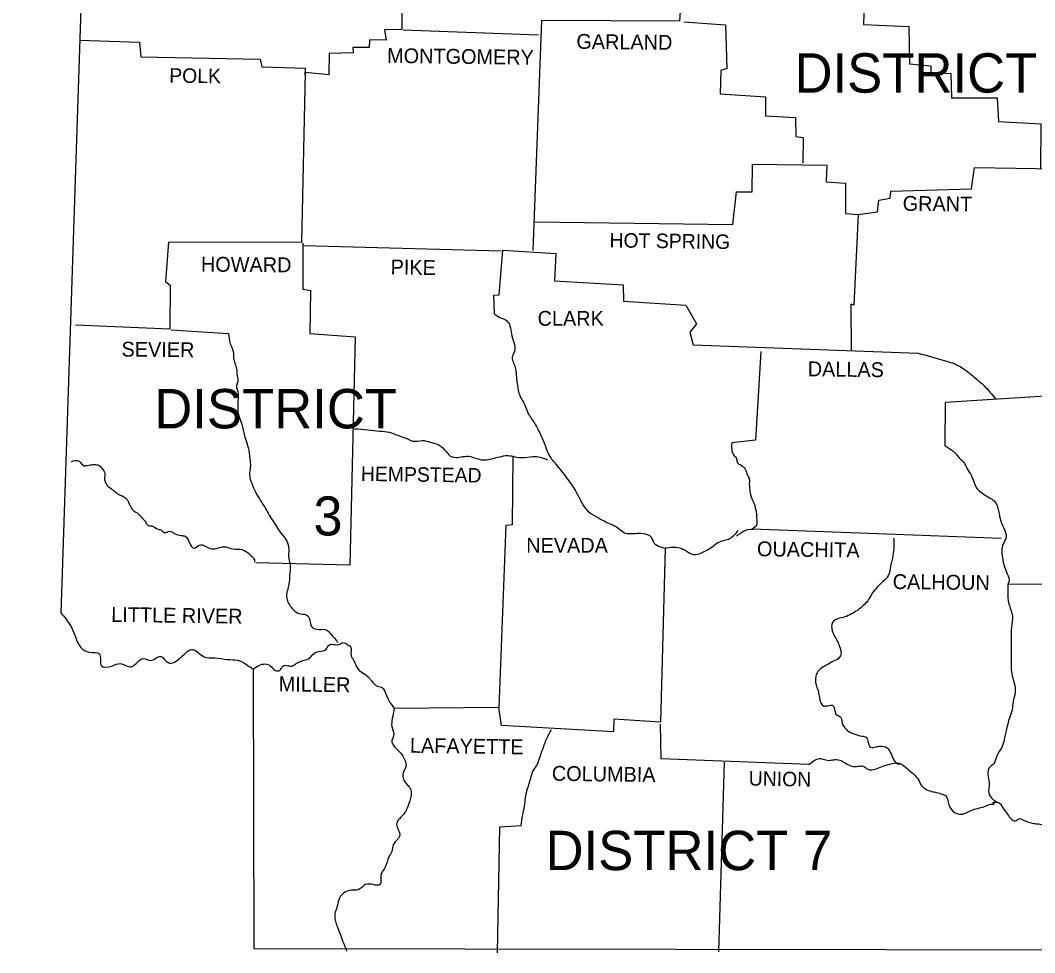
# Model space of a CAD drawing. Extents: x 1671357 to 13005564, y 567358 to 14261451.
# Drawn here: x 12758312.079 to 12758315.016, y 14259950.411 to 14259953.11 of the extents above; entities that cross this region are included whole.
import ezdxf

# ---------------------------------------------------------------- set-up
doc = ezdxf.new("R2010")
doc.units = 0
doc.layers.add('Default', color=7, linetype='Continuous')

msp = doc.modelspace()

# ---------------------------------------------------------------- linework, layer by layer
at = {"layer": 'Default'}
for points in [[(12758312.079, 14259955.7696), (12758312.286, 14259954.1076), (12758312.196, 14259951.3946)], [(12758313.186, 14259953.6686), (12758313.184, 14259953.0836), (12758313.134, 14259953.0826), (12758313.138, 14259953.0526), (12758313.09, 14259953.0536), (12758313.089, 14259953.0316), (12758313.042, 14259953.0316), (12758313.043, 14259953.0156), (12758312.973, 14259953.0136), (12758312.972, 14259952.9526), (12758312.904, 14259952.9586), (12758312.893, 14259952.4666), (12758312.508, 14259952.4676), (12758312.499, 14259952.3536), (12758312.513, 14259952.3436), (12758312.512, 14259952.2156), (12758312.239, 14259952.2276)], [(12758314.324, 14259953.2266), (12758313.997, 14259953.2366), (12758313.988, 14259953.1076), (12758313.588, 14259953.1096), (12758313.563, 14259952.4436)], [(12758314.413, 14259953.2296), (12758314.525, 14259953.2226), (12758314.521, 14259953.0976), (12758314.652, 14259953.0926), (12758314.654, 14259952.9836), (12758314.716, 14259952.9786), (12758314.716, 14259952.9596), (12758314.774, 14259952.9556), (12758314.776, 14259952.8856), (12758314.908, 14259952.8856), (12758314.912, 14259952.8166), (12758315.034, 14259952.8106), (12758315.033, 14259952.6806)], [(12758313.58, 14259953.0666), (12758313.188, 14259953.0816)], [(12758314, 14259953.1056), (12758314.121, 14259953.0966), (12758314.125, 14259952.9706), (12758314.108, 14259952.9646), (12758314.106, 14259952.8976), (12758314.237, 14259952.8886), (12758314.237, 14259952.8336), (12758314.324, 14259952.8286), (12758314.325, 14259952.7736), (12758314.346, 14259952.7706), (12758314.345, 14259952.6966)], [(12758312.251, 14259953.0526), (12758312.424, 14259953.0466), (12758312.428, 14259953.0046), (12758312.774, 14259952.9976), (12758312.778, 14259952.9756), (12758312.904, 14259952.9716), (12758312.903, 14259952.9526)], [(12758316.226, 14259952.7956), (12758315.848, 14259952.8056), (12758315.846, 14259952.6826), (12758315.081, 14259952.6796), (12758315.075, 14259952.2736), (12758315.052, 14259952.2726), (12758315.049, 14259952.0216), (12758314.757, 14259952.0036), (12758314.756, 14259951.8786)], [(12758313.57, 14259952.5266), (12758314.142, 14259952.5186), (12758314.153, 14259952.6136), (12758314.198, 14259952.6136), (12758314.199, 14259952.6936), (12758314.415, 14259952.6906), (12758314.413, 14259952.6426), (12758314.469, 14259952.6386), (12758314.469, 14259952.5506), (12758314.505, 14259952.5476), (12758314.493, 14259952.2856), (12758314.484, 14259952.2886), (12758314.485, 14259952.1526)], [(12758314.505, 14259952.5476), (12758314.561, 14259952.5556), (12758314.565, 14259952.5896), (12758314.598, 14259952.5956), (12758314.6, 14259952.6156), (12758314.833, 14259952.6226), (12758314.842, 14259952.6836), (12758315.081, 14259952.6796)], [(12758312.897, 14259952.4646), (12758312.897, 14259952.3316), (12758312.919, 14259952.3276), (12758312.917, 14259952.2036), (12758313.049, 14259952.1936), (12758313.033, 14259951.5326), (12758312.761, 14259951.5396)], [(12758312.899, 14259952.4576), (12758313.471, 14259952.4426)], [(12758313.452, 14259952.2596), (12758313.45, 14259952.3146), (12758313.466, 14259952.3156), (12758313.476, 14259952.4446), (12758313.63, 14259952.4346), (12758313.626, 14259952.3556), (12758313.825, 14259952.3446), (12758313.826, 14259952.2966), (12758314.006, 14259952.2856), (12758314.037, 14259952.2316), (12758314.018, 14259952.2076), (12758314.027, 14259952.1706), (12758314.679, 14259952.1466)], [(12758312.516, 14259952.2136), (12758312.682, 14259952.2036)], [(12758314.223, 14259952.1516), (12758314.208, 14259951.8946), (12758314.139, 14259951.8866)], [(12758313.505, 14259951.8486), (12758313.503, 14259951.6496), (12758313.485, 14259951.6476), (12758313.465, 14259951.1206)], [(12758314.198, 14259951.6376), (12758314.612, 14259951.6226), (12758314.919, 14259951.6106)], [(12758313.946, 14259951.5816), (12758313.933, 14259951.0776), (12758313.798, 14259951.0866), (12758313.797, 14259951.0496), (12758313.472, 14259951.0686), (12758313.465, 14259951.1206), (12758313.162, 14259951.1176)], [(12758314.939, 14259951.4776), (12758315.391, 14259951.4786), (12758315.381, 14259951.2006), (12758315.359, 14259951.1866)], [(12758312.753, 14259951.2316), (12758312.755, 14259950.4226), (12758316.42, 14259950.4166)], [(12758314.362, 14259950.9556), (12758313.935, 14259950.9716), (12758313.933, 14259951.0726)], [(12758314.117, 14259950.9626), (12758314.101, 14259950.4136)], [(12758313.529, 14259950.7776), (12758313.467, 14259950.7736), (12758313.46, 14259950.4106)]]:
    msp.add_lwpolyline(points, dxfattribs=at)
for points in [[(12758313.452, 14259952.2596), (12758313.468, 14259952.2496), (12758313.487, 14259952.2406), (12758313.497, 14259952.2256), (12758313.501, 14259952.2026), (12758313.508, 14259952.1776), (12758313.51, 14259952.1516), (12758313.504, 14259952.1376), (12758313.512, 14259952.1056), (12758313.515, 14259952.0836), (12758313.518, 14259952.0576), (12758313.526, 14259952.0226), (12758313.539, 14259951.9986), (12758313.551, 14259951.9696), (12758313.571, 14259951.9386), (12758313.588, 14259951.9046), (12758313.596, 14259951.8866), (12758313.611, 14259951.8496), (12758313.63, 14259951.8246), (12758313.66, 14259951.7866), (12758313.687, 14259951.7476), (12758313.702, 14259951.7186), (12758313.725, 14259951.6866), (12758313.751, 14259951.6706), (12758313.784, 14259951.6536), (12758313.805, 14259951.6436), (12758313.829, 14259951.6266), (12758313.86, 14259951.6246), (12758313.883, 14259951.6246), (12758313.904, 14259951.6156), (12758313.914, 14259951.5976), (12758313.932, 14259951.5856), (12758313.946, 14259951.5816)], [(12758312.682, 14259952.2036), (12758312.687, 14259952.1736), (12758312.696, 14259952.1476), (12758312.697, 14259952.1276), (12758312.706, 14259952.0976), (12758312.706, 14259952.0866), (12758312.709, 14259952.0646), (12758312.705, 14259952.0526), (12758312.71, 14259952.0286), (12758312.709, 14259952.0106), (12758312.709, 14259951.9956), (12758312.71, 14259951.9706), (12758312.718, 14259951.9486), (12758312.726, 14259951.9156), (12758312.731, 14259951.8986), (12758312.739, 14259951.8726), (12758312.744, 14259951.8406), (12758312.745, 14259951.8166), (12758312.743, 14259951.7946), (12758312.749, 14259951.7696), (12758312.76, 14259951.7446), (12758312.774, 14259951.7206), (12758312.791, 14259951.6936), (12758312.803, 14259951.6726), (12758312.818, 14259951.6496), (12758312.83, 14259951.6306), (12758312.848, 14259951.6066), (12758312.856, 14259951.5866), (12758312.856, 14259951.5586), (12758312.86, 14259951.5326), (12758312.859, 14259951.5036), (12758312.857, 14259951.4776), (12758312.85, 14259951.4416), (12758312.855, 14259951.4246), (12758312.874, 14259951.3996), (12758312.886, 14259951.3926), (12758312.907, 14259951.3886), (12758312.917, 14259951.3746), (12758312.923, 14259951.3536), (12758312.944, 14259951.3466), (12758312.967, 14259951.3446), (12758312.978, 14259951.3326), (12758312.993, 14259951.3166), (12758312.998, 14259951.3086)], [(12758314.679, 14259952.1466), (12758314.757, 14259952.1246), (12758314.797, 14259952.1096), (12758314.837, 14259952.0806), (12758314.87, 14259952.0516), (12758314.903, 14259952.0146)], [(12758313.047, 14259951.9276), (12758313.085, 14259951.9246), (12758313.12, 14259951.9206), (12758313.147, 14259951.9176), (12758313.175, 14259951.9076), (12758313.2, 14259951.8986), (12758313.216, 14259951.8916), (12758313.243, 14259951.8936), (12758313.266, 14259951.8886), (12758313.292, 14259951.8796), (12758313.311, 14259951.8626), (12758313.323, 14259951.8496), (12758313.346, 14259951.8446), (12758313.365, 14259951.8476), (12758313.388, 14259951.8456), (12758313.414, 14259951.8376), (12758313.435, 14259951.8386), (12758313.452, 14259951.8426), (12758313.472, 14259951.8476), (12758313.497, 14259951.8496), (12758313.516, 14259951.8456), (12758313.541, 14259951.8446), (12758313.57, 14259951.8476), (12758313.606, 14259951.8376)], [(12758314.139, 14259951.8866), (12758314.139, 14259951.8676), (12758314.146, 14259951.8496), (12758314.153, 14259951.8416), (12758314.156, 14259951.8286), (12758314.165, 14259951.8226), (12758314.178, 14259951.8106), (12758314.185, 14259951.7936), (12758314.19, 14259951.7826), (12758314.19, 14259951.7686), (12758314.191, 14259951.7546), (12758314.193, 14259951.7376), (12758314.205, 14259951.7076), (12758314.208, 14259951.6956), (12758314.21, 14259951.6856), (12758314.211, 14259951.6686), (12758314.211, 14259951.6486), (12758314.198, 14259951.6376)], [(12758314.756, 14259951.8786), (12758314.779, 14259951.8636), (12758314.798, 14259951.8436), (12758314.812, 14259951.8286), (12758314.821, 14259951.8116), (12758314.833, 14259951.7916), (12758314.85, 14259951.7536), (12758314.865, 14259951.7406), (12758314.886, 14259951.7276), (12758314.899, 14259951.7186), (12758314.912, 14259951.6896), (12758314.918, 14259951.6606), (12758314.929, 14259951.6346), (12758314.934, 14259951.6146), (12758314.925, 14259951.5946), (12758314.923, 14259951.5546), (12758314.929, 14259951.5276), (12758314.937, 14259951.5076), (12758314.942, 14259951.4846), (12758314.939, 14259951.4776)], [(12758312.227, 14259951.8326), (12758312.249, 14259951.8336), (12758312.264, 14259951.8206), (12758312.273, 14259951.8216), (12758312.289, 14259951.8236), (12758312.304, 14259951.8226), (12758312.315, 14259951.8136), (12758312.324, 14259951.7976), (12758312.323, 14259951.7826), (12758312.324, 14259951.7766), (12758312.331, 14259951.7636), (12758312.343, 14259951.7536), (12758312.356, 14259951.7436), (12758312.368, 14259951.7356), (12758312.388, 14259951.7226), (12758312.39, 14259951.7186), (12758312.398, 14259951.7026), (12758312.408, 14259951.6896), (12758312.42, 14259951.6816), (12758312.433, 14259951.6676), (12758312.439, 14259951.6616), (12758312.449, 14259951.6476), (12758312.46, 14259951.6466), (12758312.475, 14259951.6376), (12758312.486, 14259951.6346), (12758312.498, 14259951.6266), (12758312.51, 14259951.6306), (12758312.525, 14259951.6246), (12758312.545, 14259951.6186), (12758312.556, 14259951.6166), (12758312.569, 14259951.5976), (12758312.582, 14259951.5816), (12758312.598, 14259951.5906), (12758312.628, 14259951.5816), (12758312.647, 14259951.5806), (12758312.664, 14259951.5856), (12758312.677, 14259951.5846), (12758312.701, 14259951.5786), (12758312.716, 14259951.5786), (12758312.732, 14259951.5726), (12758312.747, 14259951.5606), (12758312.757, 14259951.5476), (12758312.757, 14259951.5416)], [(12758314.157, 14259951.6326), (12758314.146, 14259951.6196), (12758314.133, 14259951.6086), (12758314.118, 14259951.6036), (12758314.104, 14259951.5996), (12758314.086, 14259951.5876), (12758314.072, 14259951.5776), (12758314.053, 14259951.5686), (12758314.035, 14259951.5626), (12758314.013, 14259951.5696), (12758314.001, 14259951.5766), (12758313.988, 14259951.5816), (12758313.946, 14259951.5816)], [(12758314.153, 14259951.6166), (12758314.179, 14259951.6336), (12758314.208, 14259951.6376)], [(12758314.608, 14259951.6106), (12758314.606, 14259951.5606), (12758314.599, 14259951.5296), (12758314.592, 14259951.5016), (12758314.577, 14259951.4856), (12758314.561, 14259951.4696), (12758314.546, 14259951.4516), (12758314.533, 14259951.4296), (12758314.52, 14259951.4156), (12758314.503, 14259951.4016), (12758314.486, 14259951.3916), (12758314.467, 14259951.3826), (12758314.446, 14259951.3776), (12758314.431, 14259951.3666), (12758314.43, 14259951.3426), (12758314.447, 14259951.3086), (12758314.453, 14259951.2926), (12758314.455, 14259951.2736), (12758314.448, 14259951.2626), (12758314.432, 14259951.2536), (12758314.413, 14259951.2426), (12758314.396, 14259951.2326), (12758314.384, 14259951.2156), (12758314.382, 14259951.1926), (12758314.39, 14259951.1656), (12758314.393, 14259951.1496), (12758314.406, 14259951.1246), (12758314.416, 14259951.1256), (12758314.434, 14259951.1246), (12758314.436, 14259951.1196), (12758314.437, 14259951.1146), (12758314.441, 14259951.1016), (12758314.456, 14259951.0906), (12758314.458, 14259951.0806), (12758314.467, 14259951.0616), (12758314.482, 14259951.0486), (12758314.493, 14259951.0446), (12758314.516, 14259951.0376), (12758314.528, 14259951.0346), (12758314.541, 14259951.0056), (12758314.557, 14259951.0066), (12758314.569, 14259951.0086), (12758314.589, 14259951.0036), (12758314.598, 14259950.9916), (12758314.607, 14259950.9716), (12758314.619, 14259950.9576), (12758314.627, 14259950.9576)], [(12758314.939, 14259951.4776), (12758314.943, 14259951.4156), (12758314.952, 14259951.3856), (12758314.949, 14259951.3536), (12758314.948, 14259951.3226), (12758314.948, 14259951.2946), (12758314.948, 14259951.2676), (12758314.948, 14259951.2396), (12758314.95, 14259951.2196), (12758314.957, 14259951.1906), (12758314.96, 14259951.1636), (12758314.954, 14259951.1376), (12758314.951, 14259951.1136), (12758314.943, 14259951.0896), (12758314.936, 14259951.0626), (12758314.928, 14259951.0276), (12758314.921, 14259951.0046), (12758314.907, 14259950.9806), (12758314.898, 14259950.9586), (12758314.884, 14259950.9446), (12758314.882, 14259950.9206), (12758314.885, 14259950.8986), (12758314.883, 14259950.8786), (12758314.89, 14259950.8596), (12758314.908, 14259950.8466)], [(12758312.196, 14259951.3946), (12758312.225, 14259951.3566), (12758312.237, 14259951.3296), (12758312.254, 14259951.2946), (12758312.279, 14259951.2806), (12758312.308, 14259951.2756), (12758312.314, 14259951.2416), (12758312.344, 14259951.2406), (12758312.368, 14259951.2476), (12758312.401, 14259951.2386), (12758312.436, 14259951.2626), (12758312.456, 14259951.2566), (12758312.485, 14259951.2686), (12758312.507, 14259951.2506), (12758312.545, 14259951.2666), (12758312.579, 14259951.2886), (12758312.611, 14259951.2676), (12758312.642, 14259951.2646), (12758312.679, 14259951.2596), (12758312.708, 14259951.2576), (12758312.734, 14259951.2446), (12758312.753, 14259951.2316), (12758312.749, 14259951.2336)], [(12758312.753, 14259951.2316), (12758312.788, 14259951.2466), (12758312.803, 14259951.2416), (12758312.816, 14259951.2286), (12758312.831, 14259951.2286), (12758312.839, 14259951.2406), (12758312.854, 14259951.2416), (12758312.866, 14259951.2406), (12758312.879, 14259951.2486), (12758312.89, 14259951.2536), (12758312.905, 14259951.2586), (12758312.916, 14259951.2626), (12758312.926, 14259951.2736), (12758312.944, 14259951.2826), (12758312.965, 14259951.2896), (12758312.971, 14259951.2996), (12758312.981, 14259951.3036), (12758313.001, 14259951.3026), (12758313.014, 14259951.3086), (12758313.025, 14259951.3036), (12758313.035, 14259951.2966), (12758313.037, 14259951.2706), (12758313.045, 14259951.2566), (12758313.057, 14259951.2316), (12758313.074, 14259951.2186), (12758313.09, 14259951.2056), (12758313.096, 14259951.1976), (12758313.113, 14259951.1826), (12758313.128, 14259951.1776), (12758313.135, 14259951.1666), (12758313.146, 14259951.1406), (12758313.162, 14259951.1176)], [(12758313.162, 14259951.1176), (12758313.156, 14259951.0886), (12758313.155, 14259951.0656), (12758313.16, 14259951.0386), (12758313.155, 14259951.0256), (12758313.163, 14259951.0066), (12758313.178, 14259950.9916), (12758313.189, 14259950.9756), (12758313.196, 14259950.9526), (12758313.187, 14259950.9266), (12758313.197, 14259950.8996), (12758313.206, 14259950.8896), (12758313.211, 14259950.8736), (12758313.204, 14259950.8426), (12758313.195, 14259950.8196), (12758313.175, 14259950.7966), (12758313.169, 14259950.7856), (12758313.172, 14259950.7706), (12758313.177, 14259950.7466), (12758313.172, 14259950.7396), (12758313.159, 14259950.7226), (12758313.155, 14259950.7036), (12758313.146, 14259950.6876), (12758313.136, 14259950.6586), (12758313.123, 14259950.6346), (12758313.121, 14259950.6076), (12758313.101, 14259950.6076), (12758313.078, 14259950.6076), (12758313.057, 14259950.5926), (12758313.038, 14259950.5916), (12758313.015, 14259950.5826), (12758313.001, 14259950.5636), (12758312.996, 14259950.5426), (12758312.99, 14259950.5226), (12758312.996, 14259950.4886), (12758313.005, 14259950.4646), (12758313.012, 14259950.4456), (12758313.024, 14259950.4146)], [(12758313.529, 14259950.7776), (12758313.534, 14259950.8096), (12758313.539, 14259950.8346), (12758313.542, 14259950.8586), (12758313.548, 14259950.8856), (12758313.557, 14259950.9146), (12758313.565, 14259950.9386), (12758313.576, 14259950.9556), (12758313.583, 14259950.9756), (12758313.592, 14259950.9996), (12758313.601, 14259951.0246), (12758313.617, 14259951.0566)], [(12758314.362, 14259950.9556), (12758314.378, 14259950.9666), (12758314.393, 14259950.9726), (12758314.408, 14259950.9696), (12758314.424, 14259950.9676), (12758314.438, 14259950.9696), (12758314.456, 14259950.9666), (12758314.471, 14259950.9576), (12758314.488, 14259950.9506), (12758314.505, 14259950.9506), (12758314.52, 14259950.9506), (12758314.533, 14259950.9416), (12758314.557, 14259950.9426), (12758314.577, 14259950.9506), (12758314.597, 14259950.9566), (12758314.624, 14259950.9596), (12758314.648, 14259950.9426), (12758314.665, 14259950.9286), (12758314.679, 14259950.9126), (12758314.689, 14259950.8946), (12758314.7, 14259950.8846), (12758314.718, 14259950.8776), (12758314.732, 14259950.8746), (12758314.749, 14259950.8696), (12758314.758, 14259950.8656), (12758314.766, 14259950.8466), (12758314.779, 14259950.8206), (12758314.804, 14259950.8116), (12758314.835, 14259950.8236), (12758314.86, 14259950.8306), (12758314.878, 14259950.8366), (12758314.889, 14259950.8406), (12758314.899, 14259950.8416), (12758314.896, 14259950.8436), (12758314.908, 14259950.8466), (12758314.919, 14259950.8386), (12758314.926, 14259950.8276), (12758314.938, 14259950.8116), (12758314.949, 14259950.7976), (12758314.96, 14259950.7926), (12758314.971, 14259950.7986), (12758314.986, 14259950.7936), (12758314.999, 14259950.7886), (12758315.014, 14259950.7846), (12758315.027, 14259950.7836), (12758315.044, 14259950.7796), (12758315.057, 14259950.7726), (12758315.069, 14259950.7656), (12758315.081, 14259950.7526), (12758315.093, 14259950.7326), (12758315.097, 14259950.7166), (12758315.111, 14259950.7006), (12758315.124, 14259950.7006), (12758315.143, 14259950.6746), (12758315.15, 14259950.6646), (12758315.165, 14259950.6466), (12758315.176, 14259950.6466), (12758315.197, 14259950.6426)]]:
    msp.add_spline(points, degree=3, dxfattribs=at)

# ---------------------------------------------------------------- texts
for s, height, rotation, p in [('GARLAND', 0.04301, 359.361, (12758313.689, 14259953.0276)), ('MONTGOMERY', 0.04301, 359.2874, (12758313.141, 14259952.9866)), ('POLK', 0.04199, 359.2043, (12758312.51, 14259952.9296)), ('GRANT', 0.04301, 359.3969, (12758314.634, 14259952.5586)), ('HOT SPRING', 0.04201, 359.2152, (12758313.785, 14259952.4526)), ('HOWARD', 0.04301, 359.5103, (12758312.602, 14259952.3826)), ('PIKE', 0.043, 359.029, (12758313.151, 14259952.3746)), ('SEVIER', 0.04301, 359.4242, (12758312.372, 14259952.1366)), ('DALLAS', 0.043, 359.2395, (12758314.359, 14259952.0796)), ('HEMPSTEAD', 0.04199, 359.1815, (12758313.065, 14259951.7766)), ('OUACHITA', 0.04301, 359.1987, (12758314.212, 14259951.5586)), ('CALHOUN', 0.04301, 359.3563, (12758314.605, 14259951.4636)), ('LITTLE RIVER', 0.043008, 359.1636, (12758312.342, 14259951.3686)), ('MILLER', 0.043, 359.1406, (12758312.827, 14259951.1676)), ('LAFAYETTE', 0.043, 359.1768, (12758313.207, 14259950.9896)), ('COLUMBIA', 0.043, 359.2043, (12758313.618, 14259950.9086)), ('UNION', 0.04201, 358.9456, (12758314.188, 14259950.8946))]:
    msp.add_text(s, height=height, rotation=rotation, dxfattribs=at).set_placement(p)
for s, height, p in [('DISTRICT 6', 0.114, (12758314.321, 14259952.9006)), ('CLARK', 0.043, (12758313.577, 14259952.2256)), ('DISTRICT', 0.114, (12758312.467, 14259951.9286)), ('3', 0.113, (12758312.928, 14259951.6186)), ('NEVADA', 0.043, (12758313.544, 14259951.5686)), ('DISTRICT 7', 0.114, (12758313.6, 14259950.6496))]:
    msp.add_text(s, height=height, dxfattribs=at).set_placement(p)

doc.saveas('drawing.dxf')
